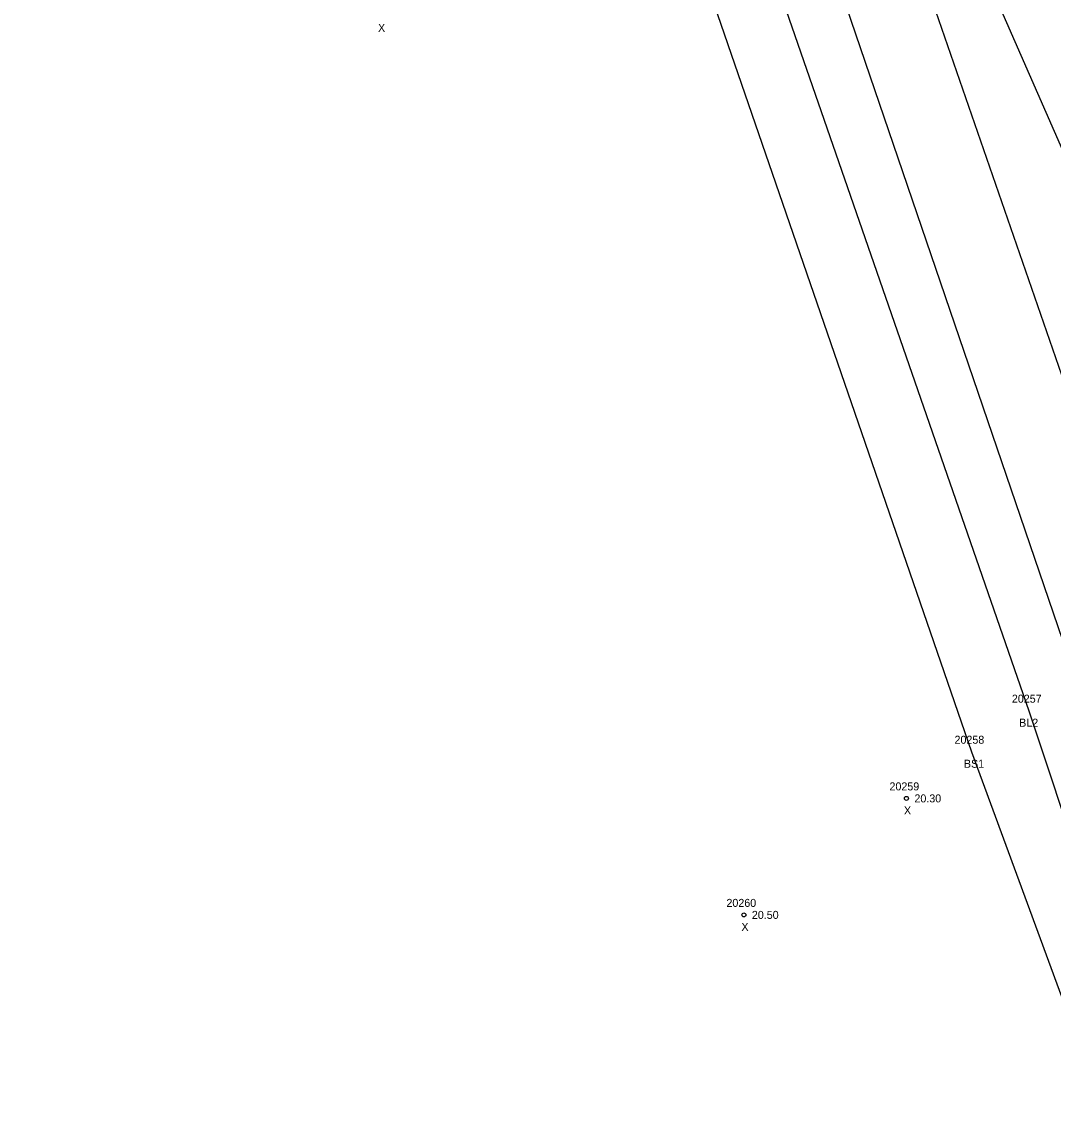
# Model space of a CAD drawing. Extents: x 2432729 to 2433340, y 684958 to 688103.
# Drawn here: x 2432899 to 2433027.9, y 686613.4 to 686750.6 of the extents above; entities that cross this region are included whole.
import ezdxf

# ---------------------------------------------------------------- set-up
doc = ezdxf.new("R2010")
doc.units = 0
for name, color, linetype in [('RD_DTM_BkLn1', 7, 'Continuous'), ('RD_DTM_BkLn2', 7, 'Continuous'), ('RD_EX_Road', 7, 'Continuous'), ('RD_Sketch8', 7, 'Continuous'), ('RD_SMD_Locator', 7, 'Continuous'), ('RD_SMD_Misc', 7, 'Continuous')]:
    doc.layers.add(name, color=color, linetype=linetype)

msp = doc.modelspace()

# ---------------------------------------------------------------- linework, layer by layer
at = {"layer": 'RD_DTM_BkLn1'}
for points in [[(2432926.02, 687213.66), (2432924.35, 687158.94), (2432925.68, 687108.84), (2432939.7, 687000.92), (2432956.93, 686927.39), (2432975, 686866.8), (2433007.19, 686769.33), (2433041.66, 686669.67), (2433075.97, 686569.51), (2433108.49, 686474.01), (2433123.82, 686426.48), (2433137.99, 686374.7), (2433148.76, 686320.1), (2433154.8, 686269.16), (2433155.78, 686212.93), (2433152.37, 686164.52), (2433145.67, 686113.9), (2433140.38, 686078.83)], [(2432898.98, 687049.37), (2432906.9, 687044.55), (2432919.33, 686997.25), (2432938.84, 686920.72), (2432957.15, 686862.46), (2432990.45, 686763.71), (2433024.84, 686664.51), (2433058.68, 686562.8), (2433090.41, 686467.11), (2433107.21, 686420.87), (2433120.26, 686369.86), (2433132.05, 686313.5), (2433136.59, 686267.4), (2433133.92, 686213.17), (2433133.74, 686165.58), (2433125.69, 686115.89), (2433123.08, 686088.41), (2433128.09, 686081.14)]]:
    msp.add_lwpolyline(points, dxfattribs=at)
at = {"layer": 'RD_DTM_BkLn2'}
msp.add_lwpolyline([(2432916.74, 686973.9), (2432925.37, 686926.35), (2432950.18, 686859.06), (2432982.46, 686761.59), (2433017.67, 686659.38), (2433053.8, 686561.16), (2433080.54, 686460.75), (2433098.39, 686424.64), (2433113.62, 686368.79), (2433123.31, 686312.63), (2433128.29, 686266.56), (2433126.49, 686214.47), (2433123.88, 686164.31), (2433114.46, 686111.82), (2433110.48, 686084.68), (2433120.95, 686072.12)], dxfattribs=at)
at = {"layer": 'RD_EX_Road'}
for points in [[(2432915.64, 687215.4), (2432913.86, 687159.12), (2432915.08, 687107.55), (2432919.97, 687053.4), (2432928.7, 686998.89), (2432946.77, 686924.59), (2432964.57, 686864), (2432997.3, 686766.34), (2433031.44, 686666.38), (2433066.06, 686565.78), (2433098.73, 686469.74), (2433113.88, 686422.91), (2433127.93, 686372.14), (2433139.1, 686314.76), (2433144.47, 686268.02), (2433145.44, 686213), (2433142.32, 686164.92), (2433135.44, 686115.75), (2433128.09, 686081.14)], [(2432937.12, 687213.43), (2432935.51, 687158.7), (2432936.54, 687110.38), (2432944.97, 687033.04), (2432950.24, 687002.26), (2432966.49, 686930.23), (2432984.9, 686870.1), (2433011.7, 686787.41), (2433010.33, 686784.51), (2433011.78, 686772.99), (2433015.37, 686760.79), (2433021.02, 686752.9), (2433031.88, 686728.09), (2433052.76, 686670.56), (2433070.23, 686619.38), (2433072.02, 686607.31)]]:
    msp.add_lwpolyline(points, dxfattribs=at)
at = {"layer": 'RD_SMD_Locator'}
for centre, radius in [((2433024.84, 686664.51), 0.001), ((2433017.67, 686659.38), 0.001), ((2433009.54, 686653.55), 0.25), ((2432989.22, 686638.99), 0.25)]:
    msp.add_circle(centre, radius, dxfattribs=at)

# ---------------------------------------------------------------- texts
at = {"layer": 'RD_Sketch8'}
for s, p in [('X', (2432943.49, 686749.34)), ('20259', (2433007.42, 686654.55)), ('20.30', (2433010.54, 686653.05)), ('X', (2433009.23, 686651.55)), ('20260', (2432987.04, 686639.99)), ('20.50', (2432990.22, 686638.49)), ('X', (2432988.91, 686636.99))]:
    msp.add_text(s, height=1, dxfattribs=at).set_placement(p)
at = {"layer": 'RD_SMD_Misc'}
for s, p in [('20257', (2433022.72, 686665.51)), ('BL2', (2433023.63, 686662.51)), ('20258', (2433015.55, 686660.38)), ('BS1', (2433016.72, 686657.38))]:
    msp.add_text(s, height=1, dxfattribs=at).set_placement(p)

doc.saveas('drawing.dxf')
